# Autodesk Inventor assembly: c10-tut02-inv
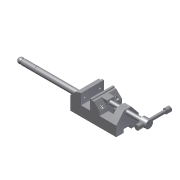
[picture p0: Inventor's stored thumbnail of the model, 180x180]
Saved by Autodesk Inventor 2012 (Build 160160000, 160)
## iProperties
Created: 2009-05
Part Number: c10-tut02-inv
Document SubType Name: Assembly
Designer: Sham
Author: Sham
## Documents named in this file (9)
- C:\Users\CadCim\Documents\SAILESH\NEW Menuscript\c10\tUT02\c10-tut02-inv.iam
- C:\Users\CadCim\Documents\SAILESH\NEW Menuscript\c10\tUT02\Base.ipt
- C:\Users\CadCim\Documents\SAILESH\NEW Menuscript\c10\tUT02\Safety Handle.ipt
- C:\Users\CadCim\Documents\SAILESH\NEW Menuscript\c10\tUT02\Jaw Face.ipt
- C:\Users\CadCim\Documents\SAILESH\NEW Menuscript\c10\tUT02\Movable Jaw.ipt
- C:\Users\CadCim\Documents\SAILESH\NEW Menuscript\c10\tUT02\Cap Screw.ipt
- C:\Users\CadCim\Documents\SAILESH\NEW Menuscript\c10\tUT02\Clamp Screw Handle.ipt
- C:\Users\CadCim\Documents\SAILESH\NEW Menuscript\c10\tUT02\Clamp Screw.ipt
- C:\Users\CadCim\Documents\SAILESH\NEW Menuscript\c10\tUT02\Handle Stop.ipt
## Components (11 placed, 8 different names)
1. Base:1 — Mate:2, Mate:3, Mate:7, Insert:10, Insert:11
2. Safety Handle:1
3. Jaw Face:1 — Insert:8, Insert:9, Mate:7
4. Jaw Face:2 — Insert:10, Insert:11
5. Movable Jaw:1 — Mate:2, Mate:3, Insert:2, Insert:3, Insert:4, Insert:8, Insert:9
6. Cap Screw:1 — Insert:2
7. Cap Screw:2 — Insert:3
8. Clamp Screw:1 — Insert:4, Mate:6, Rotation/Translation:2
9. Clamp Screw Handle:1 — Mate:6, Insert:5, Insert:6, Rotation/Translation:2
10. Handle Stop:1 — Insert:6, Mate:8
11. Handle Stop:2 — Insert:5
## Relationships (15: Insert 9, Mate 5, RelateRotateTranslate 1)
- Mate:2: Base:1 ↔ Movable Jaw:1
- Mate:3: Base:1 ↔ Movable Jaw:1
- Insert:2: Movable Jaw:1 ↔ Cap Screw:1
- Insert:3: Movable Jaw:1 ↔ Cap Screw:2
- Insert:4: Movable Jaw:1 ↔ Clamp Screw:1
- Mate:6: Clamp Screw:1 ↔ Clamp Screw Handle:1
- Insert:5: Clamp Screw Handle:1 ↔ Handle Stop:2
- Insert:6: Clamp Screw Handle:1 ↔ Handle Stop:1
- Insert:8: Jaw Face:1 ↔ Movable Jaw:1
- Insert:9: Jaw Face:1 ↔ Movable Jaw:1
- Mate:7: Base:1 ↔ Jaw Face:1
- Rotation/Translation:2 [RelateRotateTranslate]: Clamp Screw:1 ↔ Clamp Screw Handle:1
- Mate:8: Handle Stop:1
- Insert:10: Base:1 ↔ Jaw Face:2
- Insert:11: Base:1 ↔ Jaw Face:2
